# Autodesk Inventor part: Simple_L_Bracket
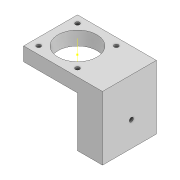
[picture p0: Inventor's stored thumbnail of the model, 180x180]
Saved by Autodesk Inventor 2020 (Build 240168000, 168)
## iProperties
Created: 2022-03
Part Number: Simple_L_Bracket
Material: Generic
Document SubType Name: Modeling
Designer: jonat
Density: 1 g/cm^3
Appearance: Default
Author: jonat
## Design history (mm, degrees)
sketch "Sketch1"
  geometry: L1 (21.5, 21.5)-(-21.5, 21.5); L2 (-21.5, 21.5)-(-21.5, -21.5); L3 (-21.5, -21.5)-(21.5, -21.5); L4 (21.5, -21.5)-(21.5, 21.5); L5 (21.5, 21.5)-(-21.5, -21.5); L6 (-21.5, 21.5)-(21.5, -21.5); 1 further point
  constraints: 12 end point, 2 midpoint, 2 parallel, 1 horizontal, 1 perpendicular
  dimensions: "d0" = 43 distance of L3.end L2.end; "d1" = 43 distance of L2.end L1.end
extrude "Extrusion1" new body sketch "Sketch1" distance "d2" = 8; taper "d3" = 0 deg
sketch "Sketch2"
  geometry: C1 r 15.5 at (0, 0); 1 further point
  constraints: 1 centre point, 1 coincident
  dimensions: "d4" = 31 diameter of C1
extrude "Extrusion2" cut sketch "Sketch2" distance "d5" = 8; taper "d6" = 0 deg
sketch "Sketch3"
  geometry: L1 (43, 8)-(0, 8) reference; L2 (0, 5)-(43, 5); L3 (43, 5)-(43, 8); L4 (43, 8)-(0, 8); L5 (0, 8)-(0, 5); 2 further points
  constraints: 8 end point, 2 parallel, 1 horizontal, 1 perpendicular
extrude "Extrusion3" join sketch "Sketch3" distance "d7" = 20; taper "d8" = 0 deg
sketch "Sketch5"
  geometry: 2 further points
hole "Hole1" sketch "Sketch5" at (15.5, 15.5) diameter "d12" = 3.4; stored, may be unused: countersink angle "d16" = 90 deg, drill point angle "d18" = 118 deg; dims "d13" = 6, "d14" = 4, "d15" = 2, "d17" = 8
pattern_circular "Circular Pattern1" dims angle "d20" = 360 deg
sketch "Sketch7"
  geometry: L1 (-21.5, -21.5)-(41.5, -21.5) reference; L2 (41.5, 21.5)-(41.5, -21.5) reference; L3 (-21.5, 21.5)-(41.5, 21.5) reference; L4 (-21.5, 21.5)-(-21.5, -21.5) reference; C1 r 15.5 at (0, 0) reference; C2 r 1.7 at (15.5, -15.5) reference; C3 r 1.7 at (-15.5, -15.5) reference; C4 r 1.7 at (-15.5, 15.5) reference; C5 r 1.7 at (15.5, 15.5) reference; C6 r 15.5 at (0, 0) reference; 1 further point
extrude "Extrusion5" join sketch "Sketch7" distance "d32" = 3; taper "d33" = 0 deg
sketch "Sketch8"
  geometry: 1 further point
sketch "Sketch9"
  geometry: L1 (0, 0)-(20, 0) reference; L2 (0, 43)-(0, 0) reference; L3 (20, 0)-(0, 0); L4 (0, 0)-(0, 43); L5 (0, 43)-(20, 43); L6 (20, 43)-(20, 0); 1 further point
  constraints: 8 end point, 2 parallel, 1 horizontal, 1 perpendicular
extrude "Extrusion6" join sketch "Sketch9" distance "d34" = 45; taper "d35" = 0 deg
sketch "Sketch11"
  geometry: L1 (43, 11)-(43, -40) reference; 2 further points
  dimensions: "d43" = 20 vertical distance of point (23, -20) point (21.5, 0); "d44" = 20 distance from line of L1 point (23, -20)
hole "Hole3" sketch "Sketch11" at (23, -20) diameter "d36" = 3.242; stored, may be unused: countersink angle "d40" = 90 deg, drill point angle "d42" = 118 deg; dims "d37" = 8, "d38" = 4, "d39" = 2, "d41" = 11.8
body "Solid1"
node "Projected Loop1"
